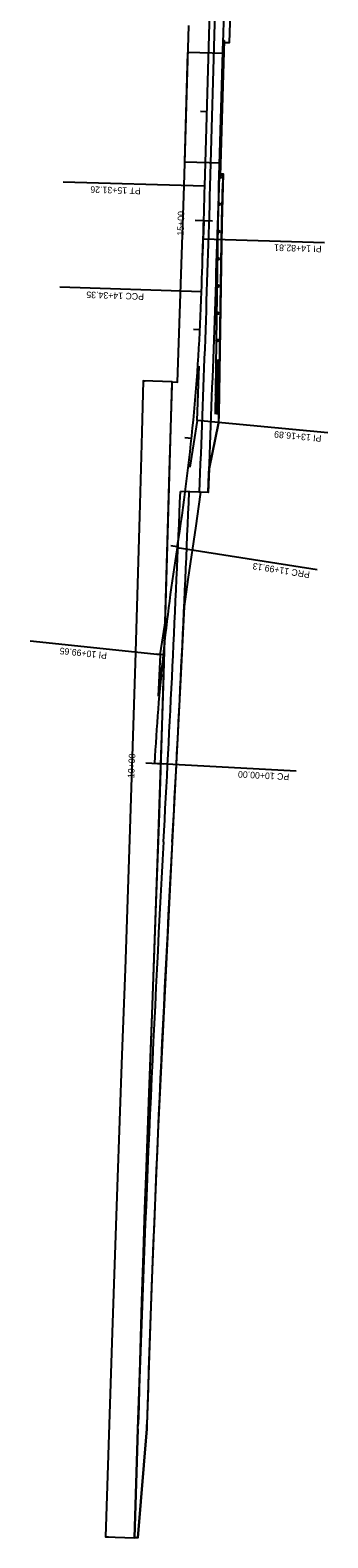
# Model space of a CAD drawing. Extents: x 1445613 to 1446340, y 2042797 to 2056486.
# Drawn here: x 1445971 to 1446244, y 2042797 to 2044179 of the extents above; entities that cross this region are included whole.
import ezdxf

# ---------------------------------------------------------------- set-up
doc = ezdxf.new("R2010")
doc.units = 0
for name, color, linetype in [('20', 7, 'Continuous'), ('Default', 7, 'Continuous'), ('R_Bridge', 7, 'Continuous'), ('R_Guardrail', 7, 'Continuous'), ('R_Horz Alg', 7, 'Continuous'), ('R_Horz Alg Annot', 7, 'Continuous'), ('R_Horz Alg Stationing', 7, 'Continuous'), ('R_Proposed Road', 7, 'Continuous'), ('R_Shld', 7, 'Continuous')]:
    doc.layers.add(name, color=color, linetype=linetype)

msp = doc.modelspace()

# ---------------------------------------------------------------- linework, layer by layer
at = {"layer": '20'}
msp.add_lwpolyline([(1446154.1, 2044195.5), (1446153.3, 2044167.5), (1446147.8, 2044167.7), (1446144.3, 2044047.7), (1446147.8, 2044047.6), (1446146.5, 2044002.4), (1446144, 2043827.1), (1446143.7, 2043819.1), (1446135, 2043777.3), (1446134.1, 2043755.5), (1446127.1, 2043755.7), (1446125.3, 2043742.6), (1446122.9, 2043725), (1446115.4, 2043675.7), (1446112, 2043650.9), (1446109.4, 2043595.6), (1446101.1, 2043435), (1446087.9, 2043168.3), (1446082.2, 2043028), (1446077.8, 2042901.4), (1446077.7, 2042897.3), (1446069.7, 2042797.5), (1446066.4, 2042797.6), (1446069.7, 2042897.5), (1446071.3, 2042948.4), (1446076.1, 2043099), (1446078.6, 2043167.1), (1446082.9, 2043285.7), (1446087.9, 2043424.4), (1446093, 2043578.2), (1446101.1, 2043856.9), (1446106.1, 2043856.7), (1446112, 2044036.7), (1446116.3, 2044183.6)], dxfattribs=at)
msp.add_lwpolyline([(1446066.4, 2042797.6), (1446069.7, 2042897.5), (1446071.3, 2042948.4), (1446073.2, 2043014.3), (1446077.1, 2043129), (1446080, 2043205.2), (1446082.9, 2043285.7), (1446086.6, 2043387.5), (1446089.3, 2043461.4), (1446091.5, 2043530.9), (1446094.4, 2043625.6), (1446098.6, 2043775.2), (1446101, 2043854.3), (1446101.1, 2043856.9), (1446074.4, 2043857.9), (1446073.4, 2043810.9), (1446071, 2043733.8), (1446067.1, 2043599), (1446061.9, 2043437.5), (1446057.9, 2043318.6), (1446055, 2043240), (1446050.5, 2043119.1), (1446046, 2042985.8), (1446040, 2042798.4)], close=True, dxfattribs=at)
at = {"layer": 'Default'}
for p, q in [((1446112.6, 2044058.7), (1446115.5, 2044158.6)), ((1446074.4, 2043857.9), (1446076.4, 2043857.8)), ((1446040, 2042798.4), (1446042.6, 2042798.3))]:
    msp.add_line(p, q, dxfattribs=at)
at = {"layer": 'R_Bridge'}
for p, q in [((1446144.3, 2044045.7), (1446147.9, 2044169.7)), ((1446145.5, 2044045.7), (1446149.1, 2044169.6)), ((1446147.9, 2044169.7), (1446149.1, 2044169.6)), ((1446148.8, 2044157.7), (1446115.5, 2044158.6)), ((1446144.3, 2044045.7), (1446145.5, 2044045.7))]:
    msp.add_line(p, q, dxfattribs=at)
msp.add_lwpolyline([(1446112.6, 2044058.7), (1446145.9, 2044057.7)], dxfattribs=at)
at = {"layer": 'R_Guardrail'}
msp.add_line((1446142.5, 2043827.1), (1446143.2, 2043877.3), dxfattribs=at)
msp.add_lwpolyline([(1446144.2, 2044044.7), (1446144, 2044035.7), (1446143, 2044002.6), (1446143, 2044002.5), (1446140.5, 2043827.2)], dxfattribs=at)
for centre in [(1446145.2, 2044044.7), (1446144.5, 2044019.7), (1446143.9, 2043994.7), (1446143.5, 2043969.7), (1446143.2, 2043944.7), (1446142.8, 2043919.8), (1446142.5, 2043894.8), (1446142.1, 2043869.8), (1446141.7, 2043844.8)]:
    msp.add_circle(centre, 1, dxfattribs=at)
at = {"layer": 'R_Horz Alg'}
msp.add_line((1446131, 2044036.1), (1446135.6, 2044196.1), dxfattribs=at)
for centre, radius, start, end in [((1423197.9, 2044703.4), 22942.8, 358.09132, 358.33333), ((1444219.2, 2044002.9), 1909.9, 351.0345, 358.0913), ((1447992.2, 2043407.6), 1909.9, 171.0345, 177.0083)]:
    msp.add_arc(centre, radius, start, end, dxfattribs=at)
at = {"layer": 'R_Horz Alg Annot'}
for p, q in [((1446130, 2044003.5), (1446129.6, 2043987.7)), ((1446129, 2043970.8), (1446129.6, 2043987.7)), ((1446240.9, 2043984.2), (1446129.6, 2043987.7)), ((1446124, 2043821.6), (1446125.7, 2043871.3)), ((1446124, 2043821.6), (1446117.3, 2043778.6)), ((1446243.8, 2043810.2), (1446124, 2043821.6)), ((1446090.2, 2043606.8), (1446095.4, 2043639.7)), ((1446090.2, 2043606.8), (1446088.2, 2043569))]:
    msp.add_line(p, q, dxfattribs=at)
for points in [[(1446131, 2044036.1), (1446001, 2044039.9)], [(1446128, 2043939.3), (1445998, 2043943.6)], [(1446105.7, 2043705.2), (1446234.1, 2043685)], [(1446090.2, 2043606.8), (1445970.8, 2043619.3)], [(1446085, 2043507.3), (1446214.8, 2043500.5)]]:
    msp.add_lwpolyline(points, dxfattribs=at)
at = {"layer": 'R_Horz Alg Stationing'}
for points in [[(1446127, 2044105), (1446133, 2044104.8)], [(1446122.1, 2044005.1), (1446138.1, 2044004.6)], [(1446120.5, 2043905.2), (1446126.5, 2043904.9)], [(1446112.8, 2043805.9), (1446118.8, 2043805.2)], [(1446099.9, 2043707), (1446105.8, 2043706.1)], [(1446086.8, 2043607.6), (1446092.8, 2043607)], [(1446077, 2043507.7), (1446093, 2043506.9)]]:
    msp.add_lwpolyline(points, dxfattribs=at)
at = {"layer": 'R_Proposed Road'}
for p, q in [((1446136, 2044036), (1446140.6, 2044195.9)), ((1446147.8, 2044167.7), (1446148.6, 2044195.7)), ((1446144, 2044035.7), (1446144.3, 2044047.7)), ((1446134.1, 2043755.5), (1446108.6, 2043756.5)), ((1446069.7, 2042897.5), (1446066.4, 2042797.6)), ((1446069.7, 2042897.5), (1446069.8, 2042901.7)), ((1446069.7, 2042797.5), (1446077.7, 2042897.3)), ((1446077.7, 2042897.3), (1446077.8, 2042901.4))]:
    msp.add_line(p, q, dxfattribs=at)
for centre, radius, start, end in [((1423197.9, 2044703.4), 22947.8, 357.63333, 358.33333), ((1423197.9, 2044703.4), 22955.8, 357.63333, 358.33333), ((1423197.9, 2044703.4), 22930.3, 356.83017, 357.63333), ((1423197.9, 2044703.4), 22938.3, 356.83017, 357.63333), ((1468964.4, 2042168.8), 22906.3, 176.83017, 178.16667), ((1468964.4, 2042168.8), 22898.3, 176.83017, 178.16667)]:
    msp.add_arc(centre, radius, start, end, dxfattribs=at)
at = {"layer": 'R_Shld'}
for p, q in [((1446147.8, 2044045.6), (1446145.5, 2044045.7)), ((1446147.4, 2044033.6), (1446147.8, 2044045.6)), ((1446144, 2043829.1), (1446146.6, 2044004.4)), ((1446135, 2043777.3), (1446143.7, 2043819.1))]:
    msp.add_line(p, q, dxfattribs=at)
for radius, start, end in [(22959.3, 358.25546, 358.33333), (22962.8, 357.79296, 357.81796)]:
    msp.add_arc((1423197.9, 2044703.4), radius, start, end, dxfattribs=at)

# ---------------------------------------------------------------- texts
at = {"layer": 'R_Horz Alg Annot'}
for s, rotation, p in [('PT 15+31.26', 178.3333, (1446072.3, 2044034.8)), ('PI 14+82.81', 178.2032, (1446238.2, 2043981.6)), ('PCC 14+34.35', 178.0913, (1446075.3, 2043938)), ('PI 13+16.89', 174.728, (1446238.2, 2043807.9)), ('PRC 11+99.13', 171.0345, (1446227.7, 2043682.9)), ('PI 10+99.65', 174.0214, (1446041.5, 2043608.9)), ('PC 10+00.00', 177.0083, (1446208.6, 2043497.8))]:
    msp.add_text(s, height=6, rotation=rotation, dxfattribs=at).set_placement(p)
at = {"layer": 'R_Horz Alg Stationing'}
for s, rotation, p in [('15+00', 88.2553, (1446111.6, 2043990.8)), ('10+00', 87.0083, (1446066.2, 2043493.6))]:
    msp.add_text(s, height=6, rotation=rotation, dxfattribs=at).set_placement(p)

doc.saveas('drawing.dxf')
